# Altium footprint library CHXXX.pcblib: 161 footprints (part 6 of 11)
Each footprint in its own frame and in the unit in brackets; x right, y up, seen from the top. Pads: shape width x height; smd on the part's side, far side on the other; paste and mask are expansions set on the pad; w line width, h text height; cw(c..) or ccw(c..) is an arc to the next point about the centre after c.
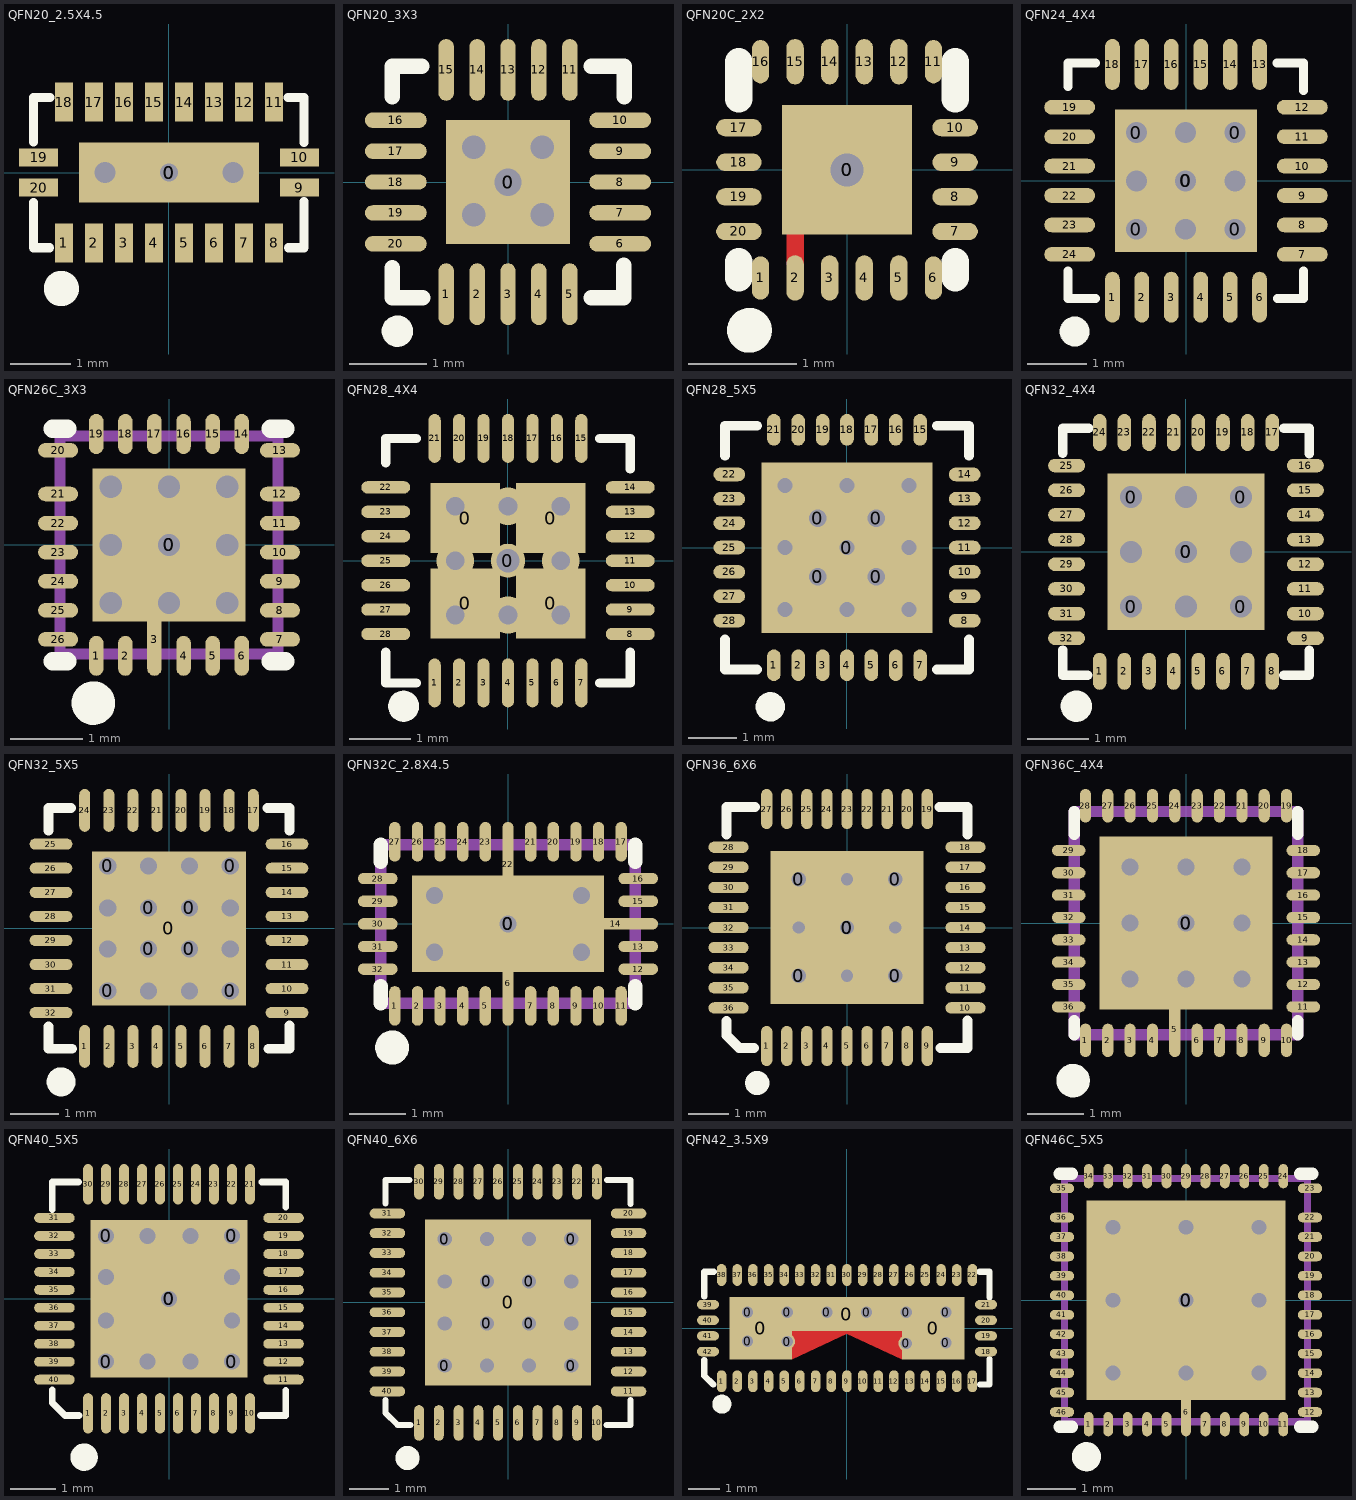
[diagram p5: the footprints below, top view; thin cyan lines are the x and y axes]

## QFN20_2.5X4.5 [mm]
pads (22):
  rect 3x1 smd mask+0.051: 0(0,0)
  round 0.559 hole 0.305 mask+0.102: 0(0,0)
  rect 0.3x0.65 smd mask+0.051: 1(-1.75,-1.17) 2(-1.25,-1.17) 3(-0.75,-1.17) 4(-0.25,-1.17) 5(0.25,-1.17) 6(0.75,-1.17) 7(1.25,-1.17) 8(1.75,-1.17) 11(1.75,1.17) 12(1.25,1.17) 13(0.75,1.17) 14(0.25,1.17) 15(-0.25,1.17) 16(-0.75,1.17) 17(-1.25,1.17) 18(-1.75,1.17)
  rect 0.65x0.3 smd mask+0.051: 9(2.17,-0.25) 10(2.17,0.25) 19(-2.17,0.25) 20(-2.17,-0.25)
via 1.064,0 diameter 0.508 hole 0.356
via -1.064,0 diameter 0.508 hole 0.356
TopOverlay:
  circle w0.35: c-1.79,-1.93 r0.118
  lines w0.152: -2.257,-0.5 -2.257,-1.251 -1.99,-1.251 ; -2.257,0.51 -2.257,1.249 -1.98,1.249 ; 1.98,1.249 2.243,1.249 2.243,0.5 ; 1.99,-1.251 2.243,-1.251 2.243,-0.48

## QFN20_3X3 [mm]
pads (22):
  rect 1.6x1.6 smd mask+0.051: 0(0,0)
  round 0.508 hole 0.356: 0(0,0)
  oval 0.2x0.8 smd mask+0.051: 1(-0.8,-1.451) 2(-0.4,-1.451) 3(0,-1.451) 4(0.4,-1.451) 5(0.8,-1.451) 11(0.8,1.451) 12(0.4,1.451) 13(0,1.451) 14(-0.4,1.451) 15(-0.8,1.451)
  oval 0.8x0.2 smd mask+0.051: 6(1.451,-0.8) 7(1.451,-0.4) 8(1.451,0) 9(1.451,0.4) 10(1.451,0.8) 16(-1.451,0.8) 17(-1.451,0.4) 18(-1.451,0) 19(-1.451,-0.4) 20(-1.451,-0.8)
via 0.442,-0.422 diameter 0.508 hole 0.305
via -0.442,0.449 diameter 0.508 hole 0.305
via -0.442,-0.422 diameter 0.508 hole 0.305
via 0.442,0.449 diameter 0.508 hole 0.305
TopOverlay:
  circle w0.203: c-1.431,-1.93 r0.102
  lines w0.203: -1.497,-1.108 -1.497,-1.5 -1.105,-1.5 ; -1.497,1.105 -1.497,1.5 -1.118,1.5 ; 1.079,-1.5 1.5,-1.5 1.5,-1.08 ; 1.082,1.5 1.503,1.5 1.503,1.108

## QFN20C_2X2 [mm]
pads (22):
  rect 1.2x1.2 smd mask+0.051: 0(0,0)
  round 0.508 hole 0.305 mask+0.051: 0(0,0)
  oval 0.16x0.4 smd mask+0.051: 1(-0.8,-1) 6(0.8,-1) 11(0.8,1) 16(-0.8,1)
  oval 0.16x0.42 smd mask+0.051: 2(-0.48,-1) 3(-0.16,-1) 4(0.16,-1) 5(0.48,-1) 12(0.48,1) 13(0.16,1) 14(-0.16,1) 15(-0.48,1)
  oval 0.42x0.16 smd mask+0.051: 7(1,-0.57) 8(1,-0.25) 9(1,0.07) 10(1,0.39) 17(-1,0.39) 18(-1,0.07) 19(-1,-0.25) 20(-1,-0.57)
TopLayer:
  rectangle: -0.56,-0.881 -0.4,-0.463
TopOverlay:
  circle w0.254: c-0.903,-1.485 r0.08
  lines w0.254: -1,-1 -1,-0.85 ; -1,0.655 -1,1 ; 1,-1 1,-0.85 ; 1,0.655 1,1
TopSolder:
  rectangle: -0.611,-0.881 -0.349,-0.463

## QFN24_4X4 [mm]
pads (30):
  round 0.508 hole 0.356: 0(-0.844,-0.823) 0(-0.844,0.818) 0(-0.005,-0.003) 0(0.833,-0.823) 0(0.833,0.818)
  rect 2.413x2.413 smd mask+0.051: 0(0,0)
  oval 0.25x0.864 smd mask+0.051: 1(-1.25,-1.976) 2(-0.75,-1.976) 3(-0.25,-1.976) 4(0.25,-1.976) 5(0.75,-1.976) 6(1.25,-1.976) 13(1.25,1.976) 14(0.75,1.976) 15(0.25,1.976) 16(-0.25,1.976) 17(-0.75,1.976) 18(-1.25,1.976)
  oval 0.864x0.25 smd mask+0.051: 7(1.976,-1.25) 8(1.976,-0.75) 9(1.976,-0.25) 10(1.976,0.25) 11(1.976,0.75) 12(1.976,1.25) 19(-1.976,1.25) 20(-1.976,0.75) 21(-1.976,0.25) 22(-1.976,-0.25) 23(-1.976,-0.75) 24(-1.976,-1.25)
via -0.005,0.818 diameter 0.508 hole 0.356
via -0.844,-0.003 diameter 0.508 hole 0.356
via -0.005,-0.823 diameter 0.508 hole 0.356
via 0.833,-0.003 diameter 0.508 hole 0.356
TopOverlay:
  circle w0.254: c-1.892,-2.56 r0.127
  lines w0.152: -2.006,-1.535 -2.006,-2 -1.537,-2 ; -2.006,1.6 -2.006,2 -1.536,2 ; 1.541,2 1.994,2 1.994,1.534 ; 1.551,-2 1.994,-2 1.994,-1.535

## QFN26C_3X3 [mm]
pads (28):
  rect 2.1x2.1 smd mask+0.051: 0(0,0)
  round 0.6 hole 0.3 mask+0.051: 0(0,0)
  oval 0.2x0.55 smd mask+0.051: 1(-1,-1.525) 2(-0.6,-1.525) 4(0.2,-1.525) 5(0.6,-1.525) 6(1,-1.525) 14(1,1.525) 15(0.6,1.525) 16(0.2,1.525) 17(-0.2,1.525) 18(-0.6,1.525) 19(-1,1.525)
  oval 0.2x1 smd mask+0.051: 3(-0.2,-1.3)
  oval 0.55x0.2 smd mask+0.051: 7(1.525,-1.3) 8(1.525,-0.9) 9(1.525,-0.5) 10(1.525,-0.1) 11(1.525,0.3) 12(1.525,0.7) 13(1.525,1.3) 20(-1.525,1.3) 21(-1.525,0.7) 22(-1.525,0.3) 23(-1.525,-0.1) 24(-1.525,-0.5) 25(-1.525,-0.9) 26(-1.525,-1.3)
via -0.8,0 diameter 0.508 hole 0.305
via -0.8,-0.8 diameter 0.508 hole 0.305
via 0,-0.8 diameter 0.508 hole 0.305
via 0.8,-0.8 diameter 0.508 hole 0.305
via 0.8,0 diameter 0.508 hole 0.305
via 0.8,0.8 diameter 0.508 hole 0.305
via 0,0.8 diameter 0.508 hole 0.305
via -0.8,0.8 diameter 0.508 hole 0.305
TopOverlay:
  circle w0.3: c-1.04,-2.175 r0.15
  lines w0.254: -1.6,-1.6 -1.4,-1.6 ; -1.6,1.6 -1.4,1.6 ; 1.4,-1.6 1.6,-1.6 ; 1.4,1.6 1.6,1.6
Mechanical15:
  lines w0.15: -1.5,-1.5 1.5,-1.5 1.5,1.5 -1.5,1.5 -1.5,-1.5

## QFN28_4X4 [mm]
pads (33):
  rect 1.143x1.143 smd mask+0: 0(-0.699,-0.699) 0(-0.699,0.698) 0(0.699,-0.699) 0(0.699,0.698)
  round 0.559 hole 0.381 mask+0.051: 0(0,0)
  oval 0.2x0.8 smd mask+0.051: 1(-1.2,-2) 2(-0.8,-2) 3(-0.4,-2) 4(0,-2) 5(0.4,-2) 6(0.8,-2) 7(1.2,-2) 15(1.2,2) 16(0.8,2) 17(0.4,2) 18(0,2) 19(-0.4,2) 20(-0.8,2) 21(-1.2,2)
  oval 0.8x0.2 smd mask+0.051: 8(2,-1.2) 9(2,-0.8) 10(2,-0.4) 11(2,0) 12(2,0.4) 13(2,0.8) 14(2,1.2) 22(-2,1.2) 23(-2,0.8) 24(-2,0.4) 25(-2,0) 26(-2,-0.4) 27(-2,-0.8) 28(-2,-1.2)
via -0.864,-0.889 diameter 0.61 hole 0.305
via 0.864,-0.889 diameter 0.61 hole 0.305
via 0.864,0.889 diameter 0.61 hole 0.305
via -0.864,0.889 diameter 0.61 hole 0.305
via -0.864,0 diameter 0.61 hole 0.305
via 0.864,0 diameter 0.61 hole 0.305
via 0,-0.889 diameter 0.61 hole 0.305
via 0,0.889 diameter 0.61 hole 0.305
TopOverlay:
  circle w0.254: c-1.708,-2.381 r0.127
  lines w0.152: -2,-1.5 -2,-2 -1.5,-2 ; -2,1.6 -2,2 -1.5,2 ; 1.5,-2 2,-2 2,-1.5 ; 1.5,2 2,2 2,1.5

## QFN28_5X5 [mm]
pads (33):
  round 0.508 hole 0.356: 0(-0.6,-0.6) 0(-0.6,0.6) 0(0.6,-0.6) 0(0.6,0.6)
  rect 3.5x3.5 smd mask+0.051: 0(0,0)
  oval 0.28x0.65 smd mask+0.051: 1(-1.5,-2.416) 2(-1,-2.416) 3(-0.5,-2.416) 4(0,-2.416) 5(0.5,-2.416) 6(1,-2.416) 7(1.5,-2.416) 15(1.5,2.416) 16(1,2.416) 17(0.5,2.416) 18(0,2.416) 19(-0.5,2.416) 20(-1,2.416) 21(-1.5,2.416)
  oval 0.65x0.28 smd mask+0.051: 8(2.416,-1.5) 9(2.416,-1) 10(2.416,-0.5) 11(2.416,0) 12(2.416,0.5) 13(2.416,1) 14(2.416,1.5) 22(-2.416,1.5) 23(-2.416,1) 24(-2.416,0.5) 25(-2.416,0) 26(-2.416,-0.5) 27(-2.416,-1) 28(-2.416,-1.5)
via 0,1.27 diameter 0.61 hole 0.305
via 1.27,1.27 diameter 0.61 hole 0.305
via 1.27,0 diameter 0.61 hole 0.305
via 1.27,-1.27 diameter 0.61 hole 0.305
via 0,-1.27 diameter 0.61 hole 0.305
via -1.27,-1.27 diameter 0.61 hole 0.305
via -1.27,0 diameter 0.61 hole 0.305
via -1.27,1.27 diameter 0.61 hole 0.305
via 0,0 diameter 0.61 hole 0.305
TopOverlay:
  circle w0.305: c-1.573,-3.268 r0.148
  lines w0.203: -2.5,-1.885 -2.5,-2.5 -1.85,-2.5 ; -2.5,1.885 -2.5,2.5 -1.85,2.5 ; 1.85,-2.5 2.5,-2.5 2.5,-1.885 ; 1.85,2.5 2.5,2.5 2.5,1.885

## QFN32_4X4 [mm]
pads (38):
  round 0.508 hole 0.356: 0(-0.889,-0.887) 0(-0.889,0.887) 0(0,0) 0(0.889,-0.887) 0(0.889,0.887)
  rect 2.54x2.54 smd mask+0.051: 0(0,0)
  oval 0.22x0.6 smd mask+0.051: 1(-1.4,-1.936) 2(-1,-1.936) 3(-0.6,-1.936) 4(-0.2,-1.936) 5(0.2,-1.936) 6(0.6,-1.936) 7(1,-1.936) 8(1.4,-1.936) 17(1.4,1.936) 18(1,1.936) 19(0.6,1.936) 20(0.2,1.936) 21(-0.2,1.936) 22(-0.6,1.936) 23(-1,1.936) 24(-1.4,1.936)
  oval 0.6x0.22 smd mask+0.051: 9(1.936,-1.4) 10(1.936,-1) 11(1.936,-0.6) 12(1.936,-0.2) 13(1.936,0.2) 14(1.936,0.6) 15(1.936,1) 16(1.936,1.4) 25(-1.936,1.4) 26(-1.936,1) 27(-1.936,0.6) 28(-1.936,0.2) 29(-1.936,-0.2) 30(-1.936,-0.6) 31(-1.936,-1) 32(-1.936,-1.4)
via 0.889,0 diameter 0.508 hole 0.356
via 0,-0.887 diameter 0.508 hole 0.356
via -0.889,0 diameter 0.508 hole 0.356
via 0,0.887 diameter 0.508 hole 0.356
TopOverlay:
  circle w0.254: c-1.78,-2.502 r0.127
  lines w0.152: -2.001,-1.591 -2.001,-1.998 -1.595,-1.998 ; -2.001,1.602 -2.001,2.002 -1.574,2.002 ; 1.583,2.002 1.999,2.002 1.999,1.59 ; 1.585,-1.998 1.999,-1.998 1.999,-1.593

## QFN32_5X5 [mil]
pads (41):
  round 20 hole 14: 0(-50.12,-51.11) 0(-50.12,51.11) 0(-16.71,-16.7) 0(-16.71,16.7) 0(16.71,-16.7) 0(16.71,16.7) 0(50.12,-51.11) 0(50.12,51.11)
  rect 125.98x125.98 smd mask+2: 0(0,0)
  oval 9x35 smd mask+2: 1(-68.9,-96.49) 2(-49.21,-96.49) 3(-29.53,-96.49) 4(-9.84,-96.49) 5(9.84,-96.49) 6(29.53,-96.49) 7(49.21,-96.49) 8(68.9,-96.49) 17(68.9,96.49) 18(49.21,96.49) 19(29.53,96.49) 20(9.84,96.49) 21(-9.84,96.49) 22(-29.53,96.49) 23(-49.21,96.49) 24(-68.9,96.49)
  oval 35x9 smd mask+2: 9(96.49,-68.9) 10(96.49,-49.21) 11(96.49,-29.53) 12(96.49,-9.84) 13(96.49,9.84) 14(96.49,29.53) 15(96.49,49.21) 16(96.49,68.9) 25(-96.49,68.9) 26(-96.49,49.21) 27(-96.49,29.53) 28(-96.49,9.84) 29(-96.49,-9.84) 30(-96.49,-29.53) 31(-96.49,-49.21) 32(-96.49,-68.9)
via -16.71,51.11 diameter 20 hole 14
via 16.71,51.11 diameter 20 hole 14
via 50.12,16.7 diameter 20 hole 14
via 50.12,-16.7 diameter 20 hole 14
via 16.71,-51.11 diameter 20 hole 14
via -16.71,-51.11 diameter 20 hole 14
via -50.12,-16.7 diameter 20 hole 14
via -50.12,16.7 diameter 20 hole 14
TopOverlay:
  circle w12: c-88.22,-125.47 r5.84
  lines w8: -98.43,-80.19 -98.43,-98.43 -79.38,-98.43 ; -98.43,79.88 -98.43,98.43 -80.12,98.43 ; 80.43,98.43 98.42,98.43 98.42,79.79 ; 81.23,-98.43 98.42,-98.43 98.42,-79.42

## QFN32C_2.8X4.5 [mm]
pads (34):
  rect 3.4x1.7 smd mask+0.051: 0(0,0)
  round 0.6 hole 0.3 mask+0.051: 0(0,0)
  oval 0.2x0.7 smd mask+0.051: 1(-2,-1.45) 2(-1.6,-1.45) 3(-1.2,-1.45) 4(-0.8,-1.45) 5(-0.4,-1.45) 7(0.4,-1.45) 8(0.8,-1.45) 9(1.2,-1.45) 10(1.6,-1.45) 11(2,-1.45) 17(2,1.45) 18(1.6,1.45) 19(1.2,1.45) 20(0.8,1.45) 21(0.4,1.45) 23(-0.4,1.45) 24(-0.8,1.45) 25(-1.2,1.45) 26(-1.6,1.45) 27(-2,1.45)
  oval 0.2x1.5 smd mask+0.051: 6(0,-1.05) 22(0,1.05)
  oval 0.7x0.2 smd mask+0.051: 12(2.3,-0.8) 13(2.3,-0.4) 15(2.3,0.4) 16(2.3,0.8) 28(-2.3,0.8) 29(-2.3,0.4) 30(-2.3,0) 31(-2.3,-0.4) 32(-2.3,-0.8)
  oval 1.5x0.2 smd mask+0.051: 14(1.9,0)
via -1.3,0.5 diameter 0.508 hole 0.305
via -1.3,-0.5 diameter 0.508 hole 0.305
via 1.3,-0.5 diameter 0.508 hole 0.305
via 1.3,0.5 diameter 0.508 hole 0.305
TopOverlay:
  circle w0.3: c-2.047,-2.185 r0.15
  lines w0.254: -2.25,-1.4 -2.25,-1.1 ; -2.25,1.1 -2.25,1.4 ; 2.25,-1.4 2.25,-1.1 ; 2.25,1.1 2.25,1.4
Mechanical15:
  lines w0.2: -2.25,-1.4 -2.25,1.4 2.25,1.4 2.25,-1.4 -2.25,-1.4

## QFN36_6X6 [mm]
pads (42):
  round 0.711 hole 0.356: 0(-1.2,-1.2) 0(-1.2,1.2) 0(0,0) 0(1.2,-1.2) 0(1.2,1.2)
  rect 3.8x3.8 smd: 0(0,0)
  oval 0.28x1 smd mask+0.051: 1(-2,-2.95) 2(-1.5,-2.95) 3(-1,-2.95) 4(-0.5,-2.95) 5(0,-2.95) 6(0.5,-2.95) 7(1,-2.95) 8(1.5,-2.95) 9(2,-2.95) 19(2,2.95) 20(1.5,2.95) 21(1,2.95) 22(0.5,2.95) 23(0,2.95) 24(-0.5,2.95) 25(-1,2.95) 26(-1.5,2.95) 27(-2,2.95)
  oval 1x0.28 smd mask+0.051: 10(2.95,-2) 11(2.95,-1.5) 12(2.95,-1) 13(2.95,-0.5) 14(2.95,0) 15(2.95,0.5) 16(2.95,1) 17(2.95,1.5) 18(2.95,2) 28(-2.95,2) 29(-2.95,1.5) 30(-2.95,1) 31(-2.95,0.5) 32(-2.95,0) 33(-2.95,-0.5) 34(-2.95,-1) 35(-2.95,-1.5) 36(-2.95,-2)
via 0,1.2 diameter 0.61 hole 0.305
via -1.2,0 diameter 0.61 hole 0.305
via 0,-1.2 diameter 0.61 hole 0.305
via 1.2,0 diameter 0.61 hole 0.305
TopOverlay:
  circle w0.305: c-2.235,-3.873 r0.148
  lines w0.254: -3,-2.328 -3,-2.684 -2.684,-3 -2.316,-3 ; -3,2.324 -3,3 -2.297,3 ; 2.311,3 3,3 3,2.317 ; 2.33,-3 3,-3 3,-2.315

## QFN36C_4X4 [mm]
pads (38):
  rect 3.1x3.1 smd mask+0.051: 0(0,0)
  round 0.6 hole 0.3 mask+0.051: 0(0,0)
  oval 0.2x0.6 smd mask+0.051: 1(-1.8,-2.1) 2(-1.4,-2.1) 3(-1,-2.1) 4(-0.6,-2.1) 6(0.2,-2.1) 7(0.6,-2.1) 8(1,-2.1) 9(1.4,-2.1) 10(1.8,-2.1) 19(1.8,2.1) 20(1.4,2.1) 21(1,2.1) 22(0.6,2.1) 23(0.2,2.1) 24(-0.2,2.1) 25(-0.6,2.1) 26(-1,2.1) 27(-1.4,2.1) 28(-1.8,2.1)
  oval 0.2x1 smd mask+0.051: 5(-0.2,-1.9)
  oval 0.6x0.2 smd mask+0.051: 11(2.1,-1.5) 12(2.1,-1.1) 13(2.1,-0.7) 14(2.1,-0.3) 15(2.1,0.1) 16(2.1,0.5) 17(2.1,0.9) 18(2.1,1.3) 29(-2.1,1.3) 30(-2.1,0.9) 31(-2.1,0.5) 32(-2.1,0.1) 33(-2.1,-0.3) 34(-2.1,-0.7) 35(-2.1,-1.1) 36(-2.1,-1.5)
via -1,1 diameter 0.508 hole 0.305
via 0,1 diameter 0.508 hole 0.305
via 1,1 diameter 0.508 hole 0.305
via 1,0 diameter 0.508 hole 0.305
via 1,-1 diameter 0.508 hole 0.305
via 0,-1 diameter 0.508 hole 0.305
via -1,-1 diameter 0.508 hole 0.305
via -1,0 diameter 0.508 hole 0.305
TopOverlay:
  circle w0.3: c-2.022,-2.821 r0.15
  lines w0.2: -2,-2 -2,-1.75 ; -2,1.59 -2,2 ; 2,-2 2,-1.75 ; 2,1.59 2,2
Mechanical15:
  lines w0.2: -2,-2 2,-2 2,2 -2,2 -2,-2

## QFN40_5X5 [mm]
pads (46):
  round 0.559 hole 0.356 mask+0.102: 0(-1.4,-1.4) 0(-1.4,1.4) 0(0,0) 0(1.4,-1.4) 0(1.4,1.4)
  rect 3.5x3.5 smd mask+0.051: 0(0,0)
  oval 0.22x0.9 smd mask+0.051: 1(-1.8,-2.55) 2(-1.4,-2.55) 3(-1,-2.55) 4(-0.6,-2.55) 5(-0.2,-2.55) 6(0.2,-2.55) 7(0.6,-2.55) 8(1,-2.55) 9(1.4,-2.55) 10(1.8,-2.55) 21(1.8,2.55) 22(1.4,2.55) 23(1,2.55) 24(0.6,2.55) 25(0.2,2.55) 26(-0.2,2.55) 27(-0.6,2.55) 28(-1,2.55) 29(-1.4,2.55) 30(-1.8,2.55)
  oval 0.9x0.22 smd mask+0.051: 11(2.55,-1.8) 12(2.55,-1.4) 13(2.55,-1) 14(2.55,-0.6) 15(2.55,-0.2) 16(2.55,0.2) 17(2.55,0.6) 18(2.55,1) 19(2.55,1.4) 20(2.55,1.8) 31(-2.55,1.8) 32(-2.55,1.4) 33(-2.55,1) 34(-2.55,0.6) 35(-2.55,0.2) 36(-2.55,-0.2) 37(-2.55,-0.6) 38(-2.55,-1) 39(-2.55,-1.4) 40(-2.55,-1.8)
via -0.483,1.4 diameter 0.61 hole 0.356
via 0.483,1.4 diameter 0.61 hole 0.356
via 1.4,0.483 diameter 0.61 hole 0.356
via 1.4,-0.483 diameter 0.61 hole 0.356
via 0.483,-1.4 diameter 0.61 hole 0.356
via -0.483,-1.4 diameter 0.61 hole 0.356
via -1.4,0.483 diameter 0.61 hole 0.356
via -1.4,-0.483 diameter 0.61 hole 0.356
TopOverlay:
  circle w0.305: c-1.89,-3.524 r0.152
  lines w0.152: -2.6,-2.025 -2.6,-2.311 -2.316,-2.6 -2.004,-2.6 ; -2.6,1.988 -2.6,2.6 -2.011,2.6 ; 2.038,-2.6 2.6,-2.6 2.6,-2.043 ; 2.065,2.6 2.6,2.6 2.6,2.039

## QFN40_6X6 [mm]
pads (49):
  round 0.508 hole 0.356 mask+0.102: 0(-1.6,-1.6) 0(-1.6,1.6) 0(-0.533,-0.533) 0(-0.533,0.533) 0(0.533,-0.533) 0(0.533,0.533) 0(1.6,-1.6) 0(1.6,1.6)
  rect 4.2x4.2 smd mask+0.051: 0(0,0)
  oval 0.25x0.9 smd mask+0.051: 1(-2.25,-3.05) 2(-1.75,-3.05) 3(-1.25,-3.05) 4(-0.75,-3.05) 5(-0.25,-3.05) 6(0.25,-3.05) 7(0.75,-3.05) 8(1.25,-3.05) 9(1.75,-3.05) 10(2.25,-3.05) 21(2.25,3.05) 22(1.75,3.05) 23(1.25,3.05) 24(0.75,3.05) 25(0.25,3.05) 26(-0.25,3.05) 27(-0.75,3.05) 28(-1.25,3.05) 29(-1.75,3.05) 30(-2.25,3.05)
  oval 0.9x0.25 smd mask+0.051: 11(3.05,-2.25) 12(3.05,-1.75) 13(3.05,-1.25) 14(3.05,-0.75) 15(3.05,-0.25) 16(3.05,0.25) 17(3.05,0.75) 18(3.05,1.25) 19(3.05,1.75) 20(3.05,2.25) 31(-3.05,2.25) 32(-3.05,1.75) 33(-3.05,1.25) 34(-3.05,0.75) 35(-3.05,0.25) 36(-3.05,-0.25) 37(-3.05,-0.75) 38(-3.05,-1.25) 39(-3.05,-1.75) 40(-3.05,-2.25)
via -0.533,1.6 diameter 0.508 hole 0.356
via 0.533,1.6 diameter 0.508 hole 0.356
via 1.6,0.533 diameter 0.508 hole 0.356
via 1.6,-0.533 diameter 0.508 hole 0.356
via 0.533,-1.6 diameter 0.508 hole 0.356
via -0.533,-1.6 diameter 0.508 hole 0.356
via -1.6,0.533 diameter 0.508 hole 0.356
via -1.6,-0.533 diameter 0.508 hole 0.356
TopOverlay:
  circle w0.305: c-2.541,-3.936 r0.152
  lines w0.152: -3.1,-2.79 -3.1,-2.794 ; -3.1,-2.466 -3.1,-2.794 ; -3.1,2.501 -3.1,3.1 -2.493,3.1 ; -2.467,-3.1 -2.794,-3.1 -3.1,-2.794 ; 2.491,-3.1 3.1,-3.1 3.1,-2.476 ; 2.502,3.1 3.1,3.1 3.1,2.484

## QFN42_3.5X9 [mm]
pads (55):
  round 0.508 hole 0.356 mask+0: 0(-3.176,-0.419) 0(-3.176,0.504) 0(-1.909,-0.429) 0(-1.909,0.504) 0(-0.642,0.504) 0(0.625,0.504) 0(1.892,-0.49) 0(1.892,0.504) 0(3.159,-0.469) 0(3.159,0.504)
  rect 2x2 smd: 0(-2.75,0) 0(2.75,0)
  rect 7.5x1.1 smd: 0(-0.002,0.45)
  oval 0.3x0.7 smd mask+0.051: 1(-4.002,-1.697) 2(-3.502,-1.697) 3(-3.002,-1.697) 4(-2.502,-1.697) 5(-2.002,-1.697) 6(-1.502,-1.697) 7(-1.002,-1.697) 8(-0.502,-1.697) 9(-0.002,-1.697) 10(0.498,-1.697) 11(0.998,-1.697) 12(1.498,-1.697) 13(2.002,-1.697) 14(2.502,-1.697) 15(3.002,-1.697) 16(3.502,-1.697) 17(4.002,-1.697) 22(4.002,1.697) 23(3.502,1.697) 24(3.002,1.697) 25(2.502,1.697) 26(2.002,1.697) 27(1.498,1.697) 28(0.998,1.697) 29(0.498,1.697) 30(-0.002,1.697) 31(-0.502,1.697) 32(-1.002,1.697) 33(-1.502,1.697) 34(-2.002,1.697) 35(-2.502,1.697) 36(-3.002,1.697) 37(-3.502,1.697) 38(-4.002,1.697)
  oval 0.7x0.3 smd mask+0.051: 18(4.438,-0.75) 19(4.438,-0.25) 20(4.438,0.25) 21(4.438,0.75) 39(-4.438,0.75) 40(-4.438,0.25) 41(-4.438,-0.25) 42(-4.438,-0.75)
TopLayer:
  region: 1.745,-1 1.745,0 -1.75,0 -1.75,-1 -0.002,-0.174
TopOverlay:
  circle w0.305: c-3.994,-2.425 r0.152
  lines w0.203: -4.552,-1.02 -4.552,-1.521 -4.273,-1.8 ; -4.552,1.01 -4.552,1.8 -4.25,1.8 ; 4.23,1.8 4.548,1.8 4.548,0.99 ; 4.25,-1.8 4.548,-1.8 4.548,-1
TopPaste:
  region: -1.75,-1 -0.002,-0.174 1.745,-1 2.356,-1 2.356,0 -2.36,0 -2.36,-1
TopSolder:
  region: -1.648,-1.102 -0.002,-0.323 1.644,-1.102 2.356,-1.102 2.356,0 -2.36,0 -2.36,-1.102

## QFN46C_5X5 [mm]
pads (48):
  rect 4.1x4.1 smd mask+0.051: 0(0,0)
  round 0.508 hole 0.305 mask+0.051: 0(0,0)
  oval 0.2x0.5 smd mask+0.051: 1(-2,-2.55) 2(-1.6,-2.55) 3(-1.2,-2.55) 4(-0.8,-2.55) 5(-0.4,-2.55) 7(0.4,-2.55) 8(0.8,-2.55) 9(1.2,-2.55) 10(1.6,-2.55) 11(2,-2.55) 24(2,2.55) 25(1.6,2.55) 26(1.2,2.55) 27(0.8,2.55) 28(0.4,2.55) 29(0,2.55) 30(-0.4,2.55) 31(-0.8,2.55) 32(-1.2,2.55) 33(-1.6,2.55) 34(-2,2.55)
  oval 0.2x1 smd mask+0.051: 6(0,-2.3)
  oval 0.5x0.2 smd mask+0.051: 12(2.55,-2.3) 13(2.55,-1.9) 14(2.55,-1.5) 15(2.55,-1.1) 16(2.55,-0.7) 17(2.55,-0.3) 18(2.55,0.1) 19(2.55,0.5) 20(2.55,0.9) 21(2.55,1.3) 22(2.55,1.7) 23(2.55,2.3) 35(-2.55,2.3) 36(-2.55,1.7) 37(-2.55,1.3) 38(-2.55,0.9) 39(-2.55,0.5) 40(-2.55,0.1) 41(-2.55,-0.3) 42(-2.55,-0.7) 43(-2.55,-1.1) 44(-2.55,-1.5) 45(-2.55,-1.9) 46(-2.55,-2.3)
via -1.5,0 diameter 0.61 hole 0.305
via -1.5,-1.5 diameter 0.61 hole 0.305
via 0,-1.5 diameter 0.61 hole 0.305
via 1.5,-1.5 diameter 0.61 hole 0.305
via 1.5,0 diameter 0.61 hole 0.305
via 1.5,1.5 diameter 0.61 hole 0.305
via 0,1.5 diameter 0.61 hole 0.305
via -1.5,1.5 diameter 0.61 hole 0.305
TopOverlay:
  circle w0.3: c-2.048,-3.218 r0.15
  lines w0.254: -2.6,-2.6 -2.343,-2.6 ; -2.6,2.6 -2.343,2.6 ; 2.343,-2.6 2.6,-2.6 ; 2.343,2.6 2.6,2.6
Mechanical15:
  lines w0.15: -2.5,-2.5 -2.5,2.5 2.5,2.5 2.5,-2.5 -2.5,-2.5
